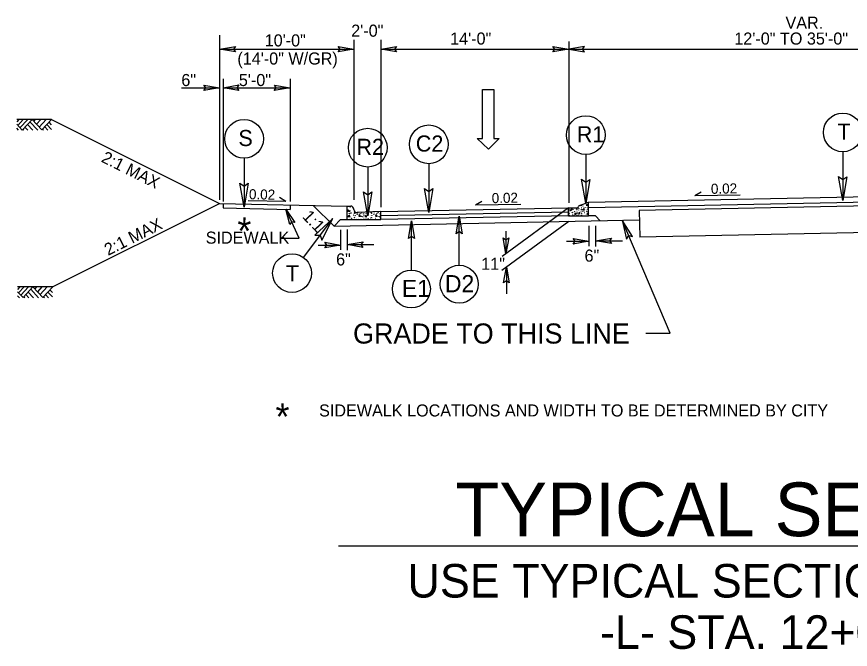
# Model space of a CAD drawing. Extents: x 1904401 to 1905163, y 193929 to 194736.
# Drawn here: x 1904516.1 to 1904578.2, y 194572.5 to 194619.6 of the extents above; entities that cross this region are included whole.
import ezdxf

# ---------------------------------------------------------------- set-up
doc = ezdxf.new("R2010")
doc.units = 0
for name, color, linetype in [('Default', 7, 'Continuous'), ('Old_Level_11', 7, 'Continuous'), ('Old_Level_20', 7, 'Continuous'), ('Prop Lane Arrow CELL', 7, 'Continuous'), ('Typical Arrow Superelevation CELL', 7, 'Continuous'), ('Typical Berm CELL', 7, 'Continuous'), ('Typical Curb CELL', 7, 'Continuous'), ('Typical Hinge Slope Arterial CELL', 7, 'Continuous'), ('Typical ID Circle CELL', 7, 'Continuous'), ('Typical Pavement Slope CELL', 7, 'Continuous'), ('Typical Terminator CELL', 7, 'Continuous'), ('Typical Text ID Circle CELL', 7, 'Continuous')]:
    doc.layers.add(name, color=color, linetype=linetype)

msp = doc.modelspace()

# ---------------------------------------------------------------- linework, layer by layer
at = {"layer": 'Default'}
for p, q in [((1904543.188, 194617.836), (1904543.188, 194605.538)), ((1904557.188, 194617.771), (1904557.188, 194605.729)), ((1904531.437, 194614.985), (1904531.437, 194605.85)), ((1904536.437, 194614.985), (1904536.437, 194605.85))]:
    msp.add_line(p, q, dxfattribs=at)
at = {"layer": 'Old_Level_11'}
for p, q in [((1904545.469, 194600.733), (1904545.469, 194604.387)), ((1904549.031, 194601.087), (1904549.031, 194604.741))]:
    msp.add_line(p, q, dxfattribs=at)
for points in [[(1904545.244, 194603.078), (1904545.469, 194604.387), (1904545.702, 194603.071), (1904545.469, 194603.238)], [(1904548.806, 194603.432), (1904549.031, 194604.741), (1904549.264, 194603.425), (1904549.031, 194603.592)]]:
    msp.add_lwpolyline(points, close=True, dxfattribs=at)
for centre in [(1904549.031, 194599.673), (1904545.469, 194599.319)]:
    msp.add_circle(centre, 1.414, dxfattribs=at)
at = {"layer": 'Prop Lane Arrow CELL'}
for p, q in [((1904531.188, 194618.239), (1904531.188, 194605.962)), ((1904541.188, 194617.881), (1904541.188, 194605.962)), ((1904543.188, 194617.881), (1904543.188, 194605.424)), ((1904531.188, 194617.188), (1904541.188, 194617.188)), ((1904543.188, 194617.188), (1904557.188, 194617.188)), ((1904557.188, 194617.188), (1904591.938, 194617.188)), ((1904531.438, 194614.985), (1904531.438, 194605.957)), ((1904528.333, 194614.313), (1904531.188, 194614.313)), ((1904531.437, 194614.313), (1904536.437, 194614.313)), ((1904550.764, 194614.174), (1904551.62, 194614.174)), ((1904550.764, 194610.543), (1904550.764, 194614.174)), ((1904551.62, 194614.174), (1904551.62, 194610.543)), ((1904516.237, 194611.956), (1904516.067, 194611.773)), ((1904516.472, 194611.159), (1904516.068, 194611.594)), ((1904516.558, 194611.956), (1904516.143, 194611.512)), ((1904516.891, 194611.956), (1904516.311, 194611.333)), ((1904517.213, 194611.955), (1904516.472, 194611.159)), ((1904517.634, 194611.151), (1904517.048, 194611.779)), ((1904517.944, 194611.169), (1904517.213, 194611.955)), ((1904517.477, 194611.956), (1904517.344, 194611.813)), ((1904517.878, 194611.956), (1904517.546, 194611.597)), ((1904518.276, 194611.956), (1904517.744, 194611.383)), ((1904518.668, 194611.948), (1904517.944, 194611.169)), ((1904518.668, 194611.547), (1904518.482, 194611.747)), ((1904516.202, 194611.151), (1904516.068, 194611.294)), ((1904516.603, 194611.151), (1904516.534, 194611.225)), ((1904516.898, 194611.151), (1904516.681, 194611.384)), ((1904517.264, 194611.151), (1904516.864, 194611.58)), ((1904518.069, 194611.151), (1904517.998, 194611.227)), ((1904518.379, 194611.151), (1904518.153, 194611.394)), ((1904518.668, 194611.214), (1904518.326, 194611.58)), ((1904551.205, 194609.726), (1904550.375, 194610.543)), ((1904550.375, 194610.543), (1904550.764, 194610.543)), ((1904552.009, 194610.543), (1904551.205, 194609.726)), ((1904551.62, 194610.543), (1904552.009, 194610.543)), ((1904537.105, 194603.096), (1904536.109, 194605.26)), ((1904557.173, 194605.361), (1904552.231, 194601.751)), ((1904557.201, 194604.355), (1904552.204, 194600.705)), ((1904564.741, 194596.017), (1904561.178, 194604.435)), ((1904540.188, 194603.739), (1904540.188, 194602.241)), ((1904540.688, 194603.74), (1904540.688, 194602.201)), ((1904552.517, 194603.631), (1904552.517, 194601.959)), ((1904558.693, 194604.019), (1904558.693, 194602.521)), ((1904559.193, 194604.02), (1904559.193, 194602.481)), ((1904535.789, 194603.096), (1904537.105, 194603.096)), ((1904559.193, 194602.903), (1904561.184, 194602.903)), ((1904538.517, 194602.595), (1904540.188, 194602.595)), ((1904540.688, 194602.623), (1904542.678, 194602.623)), ((1904557.022, 194602.875), (1904558.693, 194602.875)), ((1904552.545, 194600.953), (1904552.545, 194598.963)), ((1904516.305, 194599.47), (1904516.135, 194599.287)), ((1904516.625, 194599.47), (1904516.211, 194599.026)), ((1904516.958, 194599.47), (1904516.378, 194598.847)), ((1904517.28, 194599.469), (1904516.539, 194598.673)), ((1904517.701, 194598.665), (1904517.115, 194599.293)), ((1904518.011, 194598.683), (1904517.28, 194599.469)), ((1904517.544, 194599.47), (1904517.411, 194599.327)), ((1904517.946, 194599.47), (1904517.613, 194599.111)), ((1904518.344, 194599.47), (1904517.811, 194598.897)), ((1904518.735, 194599.462), (1904518.011, 194598.683)), ((1904518.735, 194599.06), (1904518.549, 194599.261)), ((1904516.539, 194598.673), (1904516.135, 194599.108)), ((1904516.269, 194598.665), (1904516.135, 194598.808)), ((1904516.67, 194598.665), (1904516.601, 194598.739)), ((1904516.965, 194598.665), (1904516.748, 194598.898)), ((1904517.331, 194598.665), (1904516.931, 194599.094)), ((1904518.136, 194598.665), (1904518.065, 194598.741)), ((1904518.447, 194598.665), (1904518.22, 194598.908)), ((1904518.735, 194598.728), (1904518.393, 194599.094)), ((1904562.921, 194596.017), (1904564.741, 194596.017)), ((1904540.042, 194580.172), (1904621.321, 194580.172))]:
    msp.add_line(p, q, dxfattribs=at)
for points in [[(1904518.668, 194611.956), (1904516.068, 194611.956)], [(1904518.735, 194599.47), (1904516.135, 194599.47)]]:
    msp.add_lwpolyline(points, dxfattribs=at)
at = {"layer": 'Typical Arrow Superelevation CELL'}
for p, q in [((1904536.107, 194605.841), (1904535.637, 194606.125)), ((1904566.577, 194606.278), (1904567.046, 194606.562)), ((1904566.577, 194606.278), (1904569.951, 194606.345)), ((1904536.107, 194605.841), (1904533.31, 194605.897)), ((1904550.25, 194605.582), (1904550.719, 194605.866)), ((1904550.25, 194605.582), (1904553.624, 194605.65))]:
    msp.add_line(p, q, dxfattribs=at)
at = {"layer": 'Typical Berm CELL'}
for p, q in [((1904531.188, 194605.696), (1904540.688, 194605.498)), ((1904531.437, 194605.691), (1904531.437, 194605.358)), ((1904536.437, 194605.587), (1904536.437, 194605.254)), ((1904580.438, 194605.537), (1904562.438, 194605.177)), ((1904531.437, 194605.358), (1904536.437, 194605.254)), ((1904562.438, 194605.177), (1904562.478, 194603.177)), ((1904580.438, 194603.536), (1904562.478, 194603.177))]:
    msp.add_line(p, q, dxfattribs=at)
at = {"layer": 'Typical Curb CELL'}
for p, q in [((1904540.688, 194604.498), (1904540.688, 194605.498)), ((1904540.688, 194605.498), (1904540.948, 194605.498)), ((1904557.923, 194605.455), (1904557.923, 194605.46)), ((1904557.987, 194605.549), (1904558.673, 194605.778)), ((1904558.526, 194605.606), (1904558.612, 194605.606)), ((1904558.531, 194605.52), (1904558.526, 194605.606)), ((1904558.612, 194605.606), (1904558.531, 194605.52)), ((1904558.673, 194604.778), (1904558.673, 194605.778)), ((1904540.724, 194605.12), (1904540.879, 194605.165)), ((1904540.862, 194605.074), (1904540.724, 194605.12)), ((1904540.85, 194604.801), (1904540.747, 194604.726)), ((1904540.913, 194604.687), (1904540.85, 194604.801)), ((1904540.879, 194605.165), (1904540.862, 194605.074)), ((1904541.188, 194605.248), (1904541.188, 194605.258)), ((1904543.188, 194605.081), (1904541.437, 194605.009)), ((1904541.592, 194604.857), (1904541.558, 194604.744)), ((1904541.677, 194604.738), (1904541.592, 194604.857)), ((1904542.099, 194604.801), (1904541.996, 194604.726)), ((1904542.162, 194604.687), (1904542.099, 194604.801)), ((1904542.841, 194604.857), (1904542.806, 194604.744)), ((1904542.927, 194604.738), (1904542.841, 194604.857)), ((1904543.188, 194604.498), (1904543.188, 194605.081)), ((1904557.173, 194605.361), (1904557.173, 194604.778)), ((1904557.173, 194605.361), (1904557.829, 194605.361)), ((1904557.173, 194604.778), (1904557.173, 194605.355)), ((1904557.173, 194604.778), (1904558.673, 194604.778)), ((1904557.326, 194605.229), (1904557.409, 194605.287)), ((1904557.367, 194605.139), (1904557.326, 194605.229)), ((1904557.409, 194605.287), (1904557.367, 194605.139)), ((1904557.666, 194604.972), (1904557.738, 194604.958)), ((1904557.701, 194604.849), (1904557.666, 194604.972)), ((1904557.738, 194604.958), (1904557.701, 194604.849)), ((1904558.02, 194605.014), (1904557.93, 194604.965)), ((1904557.93, 194604.965), (1904557.988, 194604.884)), ((1904557.988, 194604.884), (1904558.02, 194605.014)), ((1904558.246, 194605.245), (1904558.328, 194605.303)), ((1904558.286, 194605.154), (1904558.246, 194605.245)), ((1904558.328, 194605.303), (1904558.286, 194605.154)), ((1904558.585, 194604.988), (1904558.657, 194604.974)), ((1904558.621, 194604.865), (1904558.585, 194604.988)), ((1904558.657, 194604.974), (1904558.621, 194604.865)), ((1904540.688, 194604.498), (1904543.188, 194604.498)), ((1904540.747, 194604.726), (1904540.913, 194604.687)), ((1904541.558, 194604.744), (1904541.677, 194604.738)), ((1904541.996, 194604.726), (1904542.162, 194604.687)), ((1904542.806, 194604.744), (1904542.927, 194604.738))]:
    msp.add_line(p, q, dxfattribs=at)
for centre, radius in [((1904540.701, 194605.388), 0.00802), ((1904540.918, 194605.422), 0.00802), ((1904558.11, 194605.525), 0.00635), ((1904558.246, 194605.502), 0.00635), ((1904558.436, 194605.407), 0.00635), ((1904558.463, 194605.692), 0.00635), ((1904558.598, 194605.367), 0.00635), ((1904540.753, 194605.205), 0.00802), ((1904540.85, 194604.932), 0.00802), ((1904540.97, 194604.983), 0.00802), ((1904541.147, 194604.818), 0.00802), ((1904541.227, 194605.011), 0.00802), ((1904541.244, 194604.961), 0.00802), ((1904541.272, 194604.79), 0.00802), ((1904541.421, 194604.875), 0.00802), ((1904541.449, 194604.977), 0.00802), ((1904541.643, 194604.938), 0.00802), ((1904541.74, 194604.992), 0.00802), ((1904541.849, 194604.898), 0.00802), ((1904541.905, 194604.932), 0.00802), ((1904541.922, 194604.835), 0.00802), ((1904542.099, 194604.932), 0.00802), ((1904542.219, 194604.983), 0.00802), ((1904542.396, 194604.818), 0.00802), ((1904542.476, 194605.011), 0.00802), ((1904542.493, 194604.961), 0.00802), ((1904542.521, 194604.79), 0.00802), ((1904542.67, 194604.875), 0.00802), ((1904542.698, 194604.977), 0.00802), ((1904542.847, 194605.04), 0.00802), ((1904542.892, 194604.938), 0.00802), ((1904542.989, 194605.023), 0.00802), ((1904543.098, 194604.898), 0.00802), ((1904543.154, 194604.932), 0.00802), ((1904543.171, 194604.835), 0.00802), ((1904557.182, 194605.071), 0.00635), ((1904557.214, 194604.935), 0.00635), ((1904557.227, 194604.813), 0.00635), ((1904557.232, 194605.211), 0.00635), ((1904557.327, 194605.066), 0.00635), ((1904557.399, 194605.342), 0.00635), ((1904557.462, 194605.003), 0.00635), ((1904557.476, 194605.098), 0.00635), ((1904557.489, 194604.831), 0.00635), ((1904557.521, 194605.229), 0.00635), ((1904557.611, 194605.085), 0.00635), ((1904557.634, 194604.872), 0.00635), ((1904557.67, 194605.243), 0.00635), ((1904557.787, 194605.247), 0.00635), ((1904557.803, 194605.276), 0.00635), ((1904557.81, 194605.044), 0.00635), ((1904557.826, 194604.965), 0.00635), ((1904557.826, 194604.811), 0.00635), ((1904557.902, 194604.825), 0.00635), ((1904557.916, 194605.199), 0.00635), ((1904557.939, 194605.299), 0.00635), ((1904558.061, 194605.272), 0.00635), ((1904558.101, 194605.087), 0.00635), ((1904558.128, 194605.362), 0.00635), ((1904558.133, 194604.951), 0.00635), ((1904558.147, 194604.829), 0.00635), ((1904558.151, 194605.227), 0.00635), ((1904558.246, 194605.082), 0.00635), ((1904558.318, 194605.358), 0.00635), ((1904558.381, 194605.019), 0.00635), ((1904558.395, 194605.114), 0.00635), ((1904558.409, 194604.847), 0.00635), ((1904558.44, 194605.245), 0.00635), ((1904558.53, 194605.1), 0.00635), ((1904558.553, 194604.888), 0.00635), ((1904558.589, 194605.258), 0.00635), ((1904540.833, 194604.544), 0.00802), ((1904541.004, 194604.584), 0.00802), ((1904541.181, 194604.521), 0.00802), ((1904541.238, 194604.635), 0.00802), ((1904541.352, 194604.55), 0.00802), ((1904541.558, 194604.573), 0.00802), ((1904541.717, 194604.504), 0.00802), ((1904541.769, 194604.738), 0.00802), ((1904541.865, 194604.692), 0.00802), ((1904541.928, 194604.527), 0.00802), ((1904542.082, 194604.544), 0.00802), ((1904542.253, 194604.584), 0.00802), ((1904542.43, 194604.521), 0.00802), ((1904542.487, 194604.635), 0.00802), ((1904542.601, 194604.55), 0.00802), ((1904542.807, 194604.573), 0.00802), ((1904542.967, 194604.504), 0.00802), ((1904543.018, 194604.738), 0.00802), ((1904543.114, 194604.692), 0.00802), ((1904543.177, 194604.527), 0.00802)]:
    msp.add_circle(centre, radius, dxfattribs=at)
for centre, radius, start, end in [((1904540.948, 194605.258), 0.24, 0, 90), ((1904557.829, 194605.455), 0.0937, 270, 0), ((1904558.017, 194605.46), 0.0937, 108.43495, 180), ((1904541.427, 194605.248), 0.24, 180, 272.38446), ((1904558.639, 194604.784), 0.00635, 25.75843, 152.96144)]:
    msp.add_arc(centre, radius, start, end, dxfattribs=at)
at = {"layer": 'Typical Hinge Slope Arterial CELL'}
for p in [(1904518.668, 194611.956), (1904518.735, 194599.47)]:
    msp.add_line(p, (1904531.188, 194605.696), dxfattribs=at)
at = {"layer": 'Typical ID Circle CELL'}
for p, q in [((1904558.462, 194609.348), (1904558.462, 194605.707)), ((1904577.603, 194609.543), (1904577.603, 194605.902)), ((1904533.004, 194609.066), (1904533.004, 194605.425)), ((1904546.766, 194608.655), (1904546.766, 194605.015)), ((1904542.216, 194608.408), (1904542.216, 194604.768)), ((1904537.439, 194601.657), (1904539.609, 194604.58))]:
    msp.add_line(p, q, dxfattribs=at)
for centre in [(1904558.462, 194610.79), (1904577.603, 194610.985), (1904533.004, 194610.508), (1904542.216, 194609.851), (1904546.766, 194610.098), (1904536.579, 194600.499)]:
    msp.add_circle(centre, 1.443, dxfattribs=at)
at = {"layer": 'Typical Pavement Slope CELL'}
for p, q in [((1904558.673, 194605.778), (1904580.438, 194606.219)), ((1904539.705, 194604.005), (1904538.16, 194605.551)), ((1904558.673, 194605.391), (1904580.438, 194605.826)), ((1904543.188, 194605.081), (1904557.173, 194605.361)), ((1904543.188, 194604.79), (1904557.173, 194605.071)), ((1904557.173, 194604.778), (1904543.188, 194604.498)), ((1904559.173, 194604.768), (1904558.673, 194604.778)), ((1904559.539, 194604.402), (1904559.173, 194604.768)), ((1904539.705, 194604.005), (1904540.188, 194604.488)), ((1904539.705, 194604.005), (1904562.452, 194604.46)), ((1904540.188, 194604.488), (1904540.688, 194604.498))]:
    msp.add_line(p, q, dxfattribs=at)
at = {"layer": 'Typical Terminator CELL'}
for points in [[(1904532.359, 194616.986), (1904531.188, 194617.188), (1904532.366, 194617.396), (1904532.216, 194617.188)], [(1904540.016, 194617.389), (1904541.188, 194617.188), (1904540.009, 194616.979), (1904540.159, 194617.188)], [(1904544.359, 194616.986), (1904543.188, 194617.188), (1904544.366, 194617.396), (1904544.216, 194617.188)], [(1904556.016, 194617.389), (1904557.188, 194617.188), (1904556.009, 194616.979), (1904556.159, 194617.188)], [(1904558.359, 194617.389), (1904557.188, 194617.188), (1904558.366, 194616.979), (1904558.216, 194617.188)], [(1904530.016, 194614.515), (1904531.188, 194614.313), (1904530.009, 194614.105), (1904530.159, 194614.313)], [(1904532.609, 194614.111), (1904531.437, 194614.313), (1904532.615, 194614.521), (1904532.466, 194614.313)], [(1904535.265, 194614.515), (1904536.437, 194614.313), (1904535.259, 194614.105), (1904535.409, 194614.313)], [(1904558.769, 194607.488), (1904558.462, 194605.707), (1904558.145, 194607.498), (1904558.462, 194607.271)], [(1904577.91, 194607.683), (1904577.603, 194605.902), (1904577.286, 194607.693), (1904577.603, 194607.466)], [(1904533.311, 194607.206), (1904533.004, 194605.425), (1904532.688, 194607.216), (1904533.004, 194606.989)], [(1904547.072, 194606.796), (1904546.766, 194605.015), (1904546.449, 194606.805), (1904546.766, 194606.578)], [(1904542.523, 194606.549), (1904542.216, 194604.768), (1904541.9, 194606.559), (1904542.216, 194606.331)], [(1904536.416, 194604.112), (1904536.109, 194605.26), (1904536.791, 194604.277), (1904536.539, 194604.326)], [(1904538.793, 194602.967), (1904539.609, 194604.58), (1904538.287, 194603.33), (1904538.677, 194603.324)], [(1904561.949, 194603.234), (1904561.178, 194604.435), (1904561.499, 194603.035), (1904561.659, 194603.298)], [(1904552.719, 194603.131), (1904552.517, 194601.959), (1904552.309, 194603.138), (1904552.517, 194602.988)], [(1904557.522, 194603.077), (1904558.693, 194602.875), (1904557.515, 194602.667), (1904557.665, 194602.875)], [(1904560.365, 194602.701), (1904559.193, 194602.903), (1904560.371, 194603.111), (1904560.222, 194602.903)], [(1904539.017, 194602.797), (1904540.188, 194602.595), (1904539.01, 194602.387), (1904539.16, 194602.595)], [(1904541.86, 194602.421), (1904540.688, 194602.623), (1904541.866, 194602.831), (1904541.716, 194602.623)], [(1904552.343, 194599.782), (1904552.545, 194600.953), (1904552.753, 194599.775), (1904552.545, 194599.925)]]:
    msp.add_lwpolyline(points, close=True, dxfattribs=at)

# ---------------------------------------------------------------- texts
at = {"layer": 'Old_Level_20'}
for s, p in [('E1', (1904544.761, 194598.721)), ('D2', (1904547.966, 194599.075))]:
    msp.add_text(s, height=1.2792, dxfattribs=at).set_placement(p)
at = {"layer": 'Prop Lane Arrow CELL'}
for s, height, p in [('VAR.', 0.9, (1904573.337, 194618.711)), ('2\'-0"', 0.9, (1904540.989, 194618.118)), ('14\'-0"', 0.9, (1904548.354, 194617.531)), ('12\'-0" TO 35\'-0"', 0.9, (1904569.525, 194617.531)), ('10\'-0" ', 0.9, (1904534.542, 194617.394)), ('(14\'-0" W/GR)', 0.9, (1904532.508, 194616.044)), ('6"', 0.9, (1904528.333, 194614.44)), ('5\'-0"', 0.9, (1904532.618, 194614.44)), ('*', 2, (1904532.508, 194602.647)), ('SIDEWALK', 0.9, (1904530.15, 194602.695)), ('*', 2, (1904535.349, 194588.81)), ('SIDEWALK LOCATIONS AND WIDTH TO BE DETERMINED BY CITY', 0.9, (1904538.594, 194589.817)), ('TYPICAL SECTION NO. 1', 4, (1904548.743, 194580.898)), ('USE TYPICAL SECTION NO. 1', 2.5, (1904545.178, 194576.327)), ('-L- STA. 12+00.00 TO 15+00.00', 2.5, (1904559.52, 194572.502))]:
    msp.add_text(s, height=height, dxfattribs=at).set_placement(p)
for s, height, rotation, p in [('0.02', 0.7499, 358.8538, (1904533.364, 194606.009)), ('0.02', 0.7499, 1.1462, (1904567.788, 194606.407)), ('0.02', 0.7499, 1.1462, (1904551.461, 194605.712)), ('1:1', 0.9, 314.13194, (1904537.291, 194604.67)), ('6"', 0.9, 359.99984, (1904558.367, 194601.355)), ('6"', 0.9, 359.99984, (1904539.862, 194601.076)), ('11"', 0.9, 359.99984, (1904550.673, 194600.747)), ('GRADE TO THIS LINE', 1.5, 359.99984, (1904541.122, 194595.251))]:
    msp.add_text(s, height=height, rotation=rotation, dxfattribs=at).set_placement(p)
at = {"layer": 'Typical Hinge Slope Arterial CELL'}
for rotation, p in [(333.43495, (1904522.304, 194608.824)), (26.56505, (1904522.878, 194601.781))]:
    msp.add_text('2:1 MAX', height=0.9, rotation=rotation, dxfattribs=at).set_placement(p)
at = {"layer": 'Typical Text ID Circle CELL'}
for s, p in [('T', (1904577.21, 194610.445)), ('S', (1904532.583, 194609.968)), ('R1', (1904557.791, 194610.25)), ('R2', (1904541.374, 194609.31)), ('C2', (1904545.8, 194609.557))]:
    msp.add_text(s, height=1.2, rotation=360, dxfattribs=at).set_placement(p)
msp.add_text('T', height=1.2, dxfattribs=at).set_placement((1904536.123, 194599.887))

doc.saveas('drawing.dxf')
